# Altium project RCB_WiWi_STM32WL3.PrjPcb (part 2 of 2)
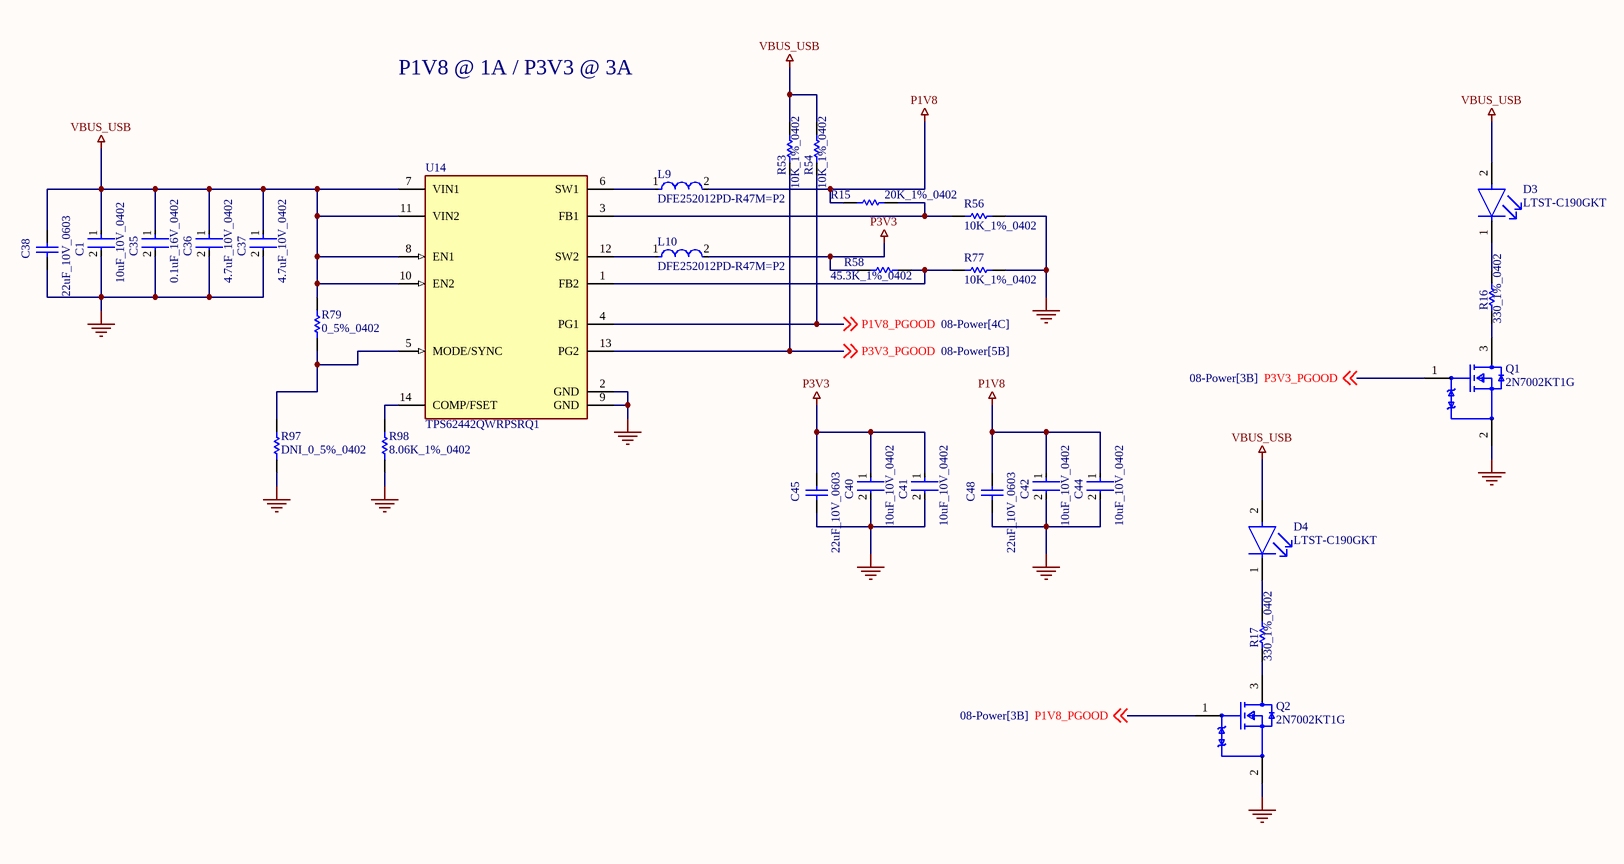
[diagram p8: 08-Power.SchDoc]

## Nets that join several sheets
DPLL_VDD_CLK: 02-8A34004_DPLL-1 (U11.48), 03-8A34004_DPLL-2 (C94.1 C95.1 L11.2)
DPLL_VDD_DCO_Q8: 02-8A34004_DPLL-1 (U11.38), 03-8A34004_DPLL-2 (C62.1 C63.1 L4.2)
DPLL_VDD_DCO_Q9: 02-8A34004_DPLL-1 (U11.31), 03-8A34004_DPLL-2 (C77.1 C78.1 L5.2)
DPLL_VDD_DCO_Q10: 02-8A34004_DPLL-1 (U11.30), 03-8A34004_DPLL-2 (C87.1 C88.1 L7.2)
DPLL_VDD_DCO_Q11: 02-8A34004_DPLL-1 (U11.23), 03-8A34004_DPLL-2 (C97.1 C98.1 L12.2)
DPLL_VDD_DIG: 02-8A34004_DPLL-1 (U11.6), 03-8A34004_DPLL-2 (5 pins)
DPLL_VDD_GPIO: 02-8A34004_DPLL-1 (U11.13), 03-8A34004_DPLL-2 (5 pins)
DPLL_VDDA_BG_LC: 02-8A34004_DPLL-1 (U11.15 U11.16), 03-8A34004_DPLL-2 (C68.1 C69.1 C70.1 L3.2)
DPLL_VDDA_FB: 02-8A34004_DPLL-1 (U11.47), 03-8A34004_DPLL-2 (C109.1 C110.1 L15.2)
DPLL_VDDA_PDCP_XTAL: 02-8A34004_DPLL-1 (U11.46), 03-8A34004_DPLL-2 (C84.1 C85.1 L6.2)
DPLL_VDDO_Q8: 02-8A34004_DPLL-1 (U11.39), 03-8A34004_DPLL-2 (C102.1 C103.1 L13.2)
DPLL_VDDO_Q9: 02-8A34004_DPLL-1 (U11.35), 03-8A34004_DPLL-2 (C92.1 C93.1 L8.2)
DPLL_VDDO_Q10: 02-8A34004_DPLL-1 (U11.26), 03-8A34004_DPLL-2 (C114.1 C115.1 L16.2)
DPLL_VDDO_Q11: 02-8A34004_DPLL-1 (U11.22), 03-8A34004_DPLL-2 (C107.1 C108.1 L14.2)
GND: 01-Antennas (25 pins), 02-8A34004_DPLL-1 (20 pins), 03-8A34004_DPLL-2 (53 pins), 04-TCXO_Crystal (12 pins), 05-USB-Prog (50 pins), 06-STM32WL3-RX (29 pins), 07-STM32WL3-TX (28 pins), 08-Power (19 pins)
P1V8: 03-8A34004_DPLL-2 (13 pins), 08-Power (5 pins)
P3V3: 02-8A34004_DPLL-1 (13 pins), 03-8A34004_DPLL-2 (21 pins), 04-TCXO_Crystal (10 pins), 05-USB-Prog (R69.1), 06-STM32WL3-RX (21 pins), 07-STM32WL3-TX (22 pins), 08-Power (5 pins)
RX_VFBSD: 01-Antennas (C13.1 C14.2 L21.2), 06-STM32WL3-RX (6 pins)
TX_VFBSD: 01-Antennas (C2.1 C3.2 L1.2), 07-STM32WL3-TX (6 pins)
VBUS_USB: 05-USB-Prog (9 pins), 08-Power (14 pins)
DPLL_CLKIN0_P: 02-8A34004_DPLL-1 (R34.1), 06-STM32WL3-RX (U5.9)
DPLL_CLKIN1_P: 02-8A34004_DPLL-1 (R36.1), 06-STM32WL3-RX (R76.2)
DPLL_CLKOUT8_N: 02-8A34004_DPLL-1 (R33.2), 07-STM32WL3-TX (R107.1)
DPLL_CLKOUT8_P: 02-8A34004_DPLL-1 (R39.2), 06-STM32WL3-RX (R86.1)
DPLL_CLKOUT10_P: 02-8A34004_DPLL-1 (R41.2), 06-STM32WL3-RX (U5.7)
DPLL_CS: 02-8A34004_DPLL-1 (R46.1 U11.9), 07-STM32WL3-TX (U7.8)
DPLL_GPIO3: 02-8A34004_DPLL-1 (U11.19), 07-STM32WL3-TX (U7.7)
DPLL_GPIO4: 02-8A34004_DPLL-1 (U11.37), 07-STM32WL3-TX (U7.11)
DPLL_GPIO5: 02-8A34004_DPLL-1 (U11.36), 07-STM32WL3-TX (U7.12)
DPLL_OSCI: 02-8A34004_DPLL-1 (U11.45), 04-TCXO_Crystal (C21.2)
DPLL_RST_N: 02-8A34004_DPLL-1 (R31.1 U11.17), 07-STM32WL3-TX (U7.19)
DPLL_SCLK: 02-8A34004_DPLL-1 (R49.1 U11.12), 07-STM32WL3-TX (U7.15)
DPLL_SDI: 02-8A34004_DPLL-1 (R45.1 U11.10), 07-STM32WL3-TX (U7.9)
DPLL_SDIO: 02-8A34004_DPLL-1 (R50.1 U11.11), 07-STM32WL3-TX (U7.16)
RX_BOOTSEL: 05-USB-Prog (R59.2), 06-STM32WL3-RX (R75.1 SW1.1 U5.10)
RX_RF_RX: 01-Antennas (C20.1 L25.1), 06-STM32WL3-RX (U5.23)
RX_RF_TX: 01-Antennas (R5.1), 06-STM32WL3-RX (U5.26)
RX_RF_TX_HP: 01-Antennas (R6.1), 06-STM32WL3-RX (U5.25)
RX_RST_N: 05-USB-Prog (R57.2), 06-STM32WL3-RX (R78.2 SW2.1 U5.36), 07-STM32WL3-TX (U7.43)
RX_RX_SEQUENCE: 06-STM32WL3-RX (R76.1), 07-STM32WL3-TX (U7.42)
RX_SPI1_MISO: 06-STM32WL3-RX (U5.35), 07-STM32WL3-TX (U7.34)
RX_SPI1_MOSI: 06-STM32WL3-RX (U5.34), 07-STM32WL3-TX (U7.35)
RX_SPI1_NSS: 06-STM32WL3-RX (U5.33), 07-STM32WL3-TX (U7.33)
RX_SPI1_SCK: 06-STM32WL3-RX (U5.32), 07-STM32WL3-TX (U7.32)
RX_SPI3_MISO: 06-STM32WL3-RX (U5.5), 07-STM32WL3-TX (U7.31)
RX_SPI3_MOSI: 06-STM32WL3-RX (U5.31), 07-STM32WL3-TX (U7.5)
RX_SPI3_NSS: 06-STM32WL3-RX (U5.6), 07-STM32WL3-TX (U7.6)
RX_SPI3_SCK: 06-STM32WL3-RX (U5.13), 07-STM32WL3-TX (U7.13)
RX_TX_SEQUENCE: 06-STM32WL3-RX (U5.19), 07-STM32WL3-TX (U7.44)
RX_USART1_RX: 05-USB-Prog (R11.2), 06-STM32WL3-RX (U5.45)
RX_USART1_TX: 05-USB-Prog (R12.2), 06-STM32WL3-RX (U5.30)
TCXO_10M: 02-8A34004_DPLL-1 (U11.1), 04-TCXO_Crystal (R26.1)
TX_BOOTSEL: 05-USB-Prog (R68.2), 07-STM32WL3-TX (R100.1 SW3.1 U7.10)
TX_LPUART_RX: 06-STM32WL3-RX (U5.4), 07-STM32WL3-TX (U7.14)
TX_LPUART_TX: 06-STM32WL3-RX (U5.14), 07-STM32WL3-TX (U7.4)
TX_RF_RX: 01-Antennas (C9.1 L20.1), 07-STM32WL3-TX (U7.23)
TX_RF_TX: 01-Antennas (R1.1), 07-STM32WL3-TX (U7.26)
TX_RF_TX_HP: 01-Antennas (R2.1), 07-STM32WL3-TX (U7.25)
TX_RST_N: 05-USB-Prog (R67.2), 07-STM32WL3-TX (R101.2 SW4.1 U7.36)
TX_RX_SPARE0: 06-STM32WL3-RX (U5.48), 07-STM32WL3-TX (U7.48)
TX_RX_SPARE2: 06-STM32WL3-RX (U5.20), 07-STM32WL3-TX (U7.20)
TX_USART1_RX: 05-USB-Prog (R62.2), 07-STM32WL3-TX (U7.45)
TX_USART1_TX: 05-USB-Prog (R63.2), 07-STM32WL3-TX (U7.30)

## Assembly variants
845-XXXXX_PCBA_projectname: all parts fitted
